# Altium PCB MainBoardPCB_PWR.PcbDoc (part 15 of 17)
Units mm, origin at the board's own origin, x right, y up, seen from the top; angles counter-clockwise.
Board outline 333.63 x 349.38 mm, 16 copper layers (L1, L2 (GND), L3 (Sign), L4 (GND), L5 (Sign), L6 (PWR/GND), L7(PWR/GND), L8 (PWR/GND), L9 (PWR/GND), L10 (PWR/GND), L11 (PWR/GND), L12 (Sign), L13 (GND), L14 (Sign), L15 (GND), L16), stack 2.503 mm thick; 2187 components, 1615 nets, 7987 pads, 1695 vias.
Unrouted connection lines stored in the file: 4757.
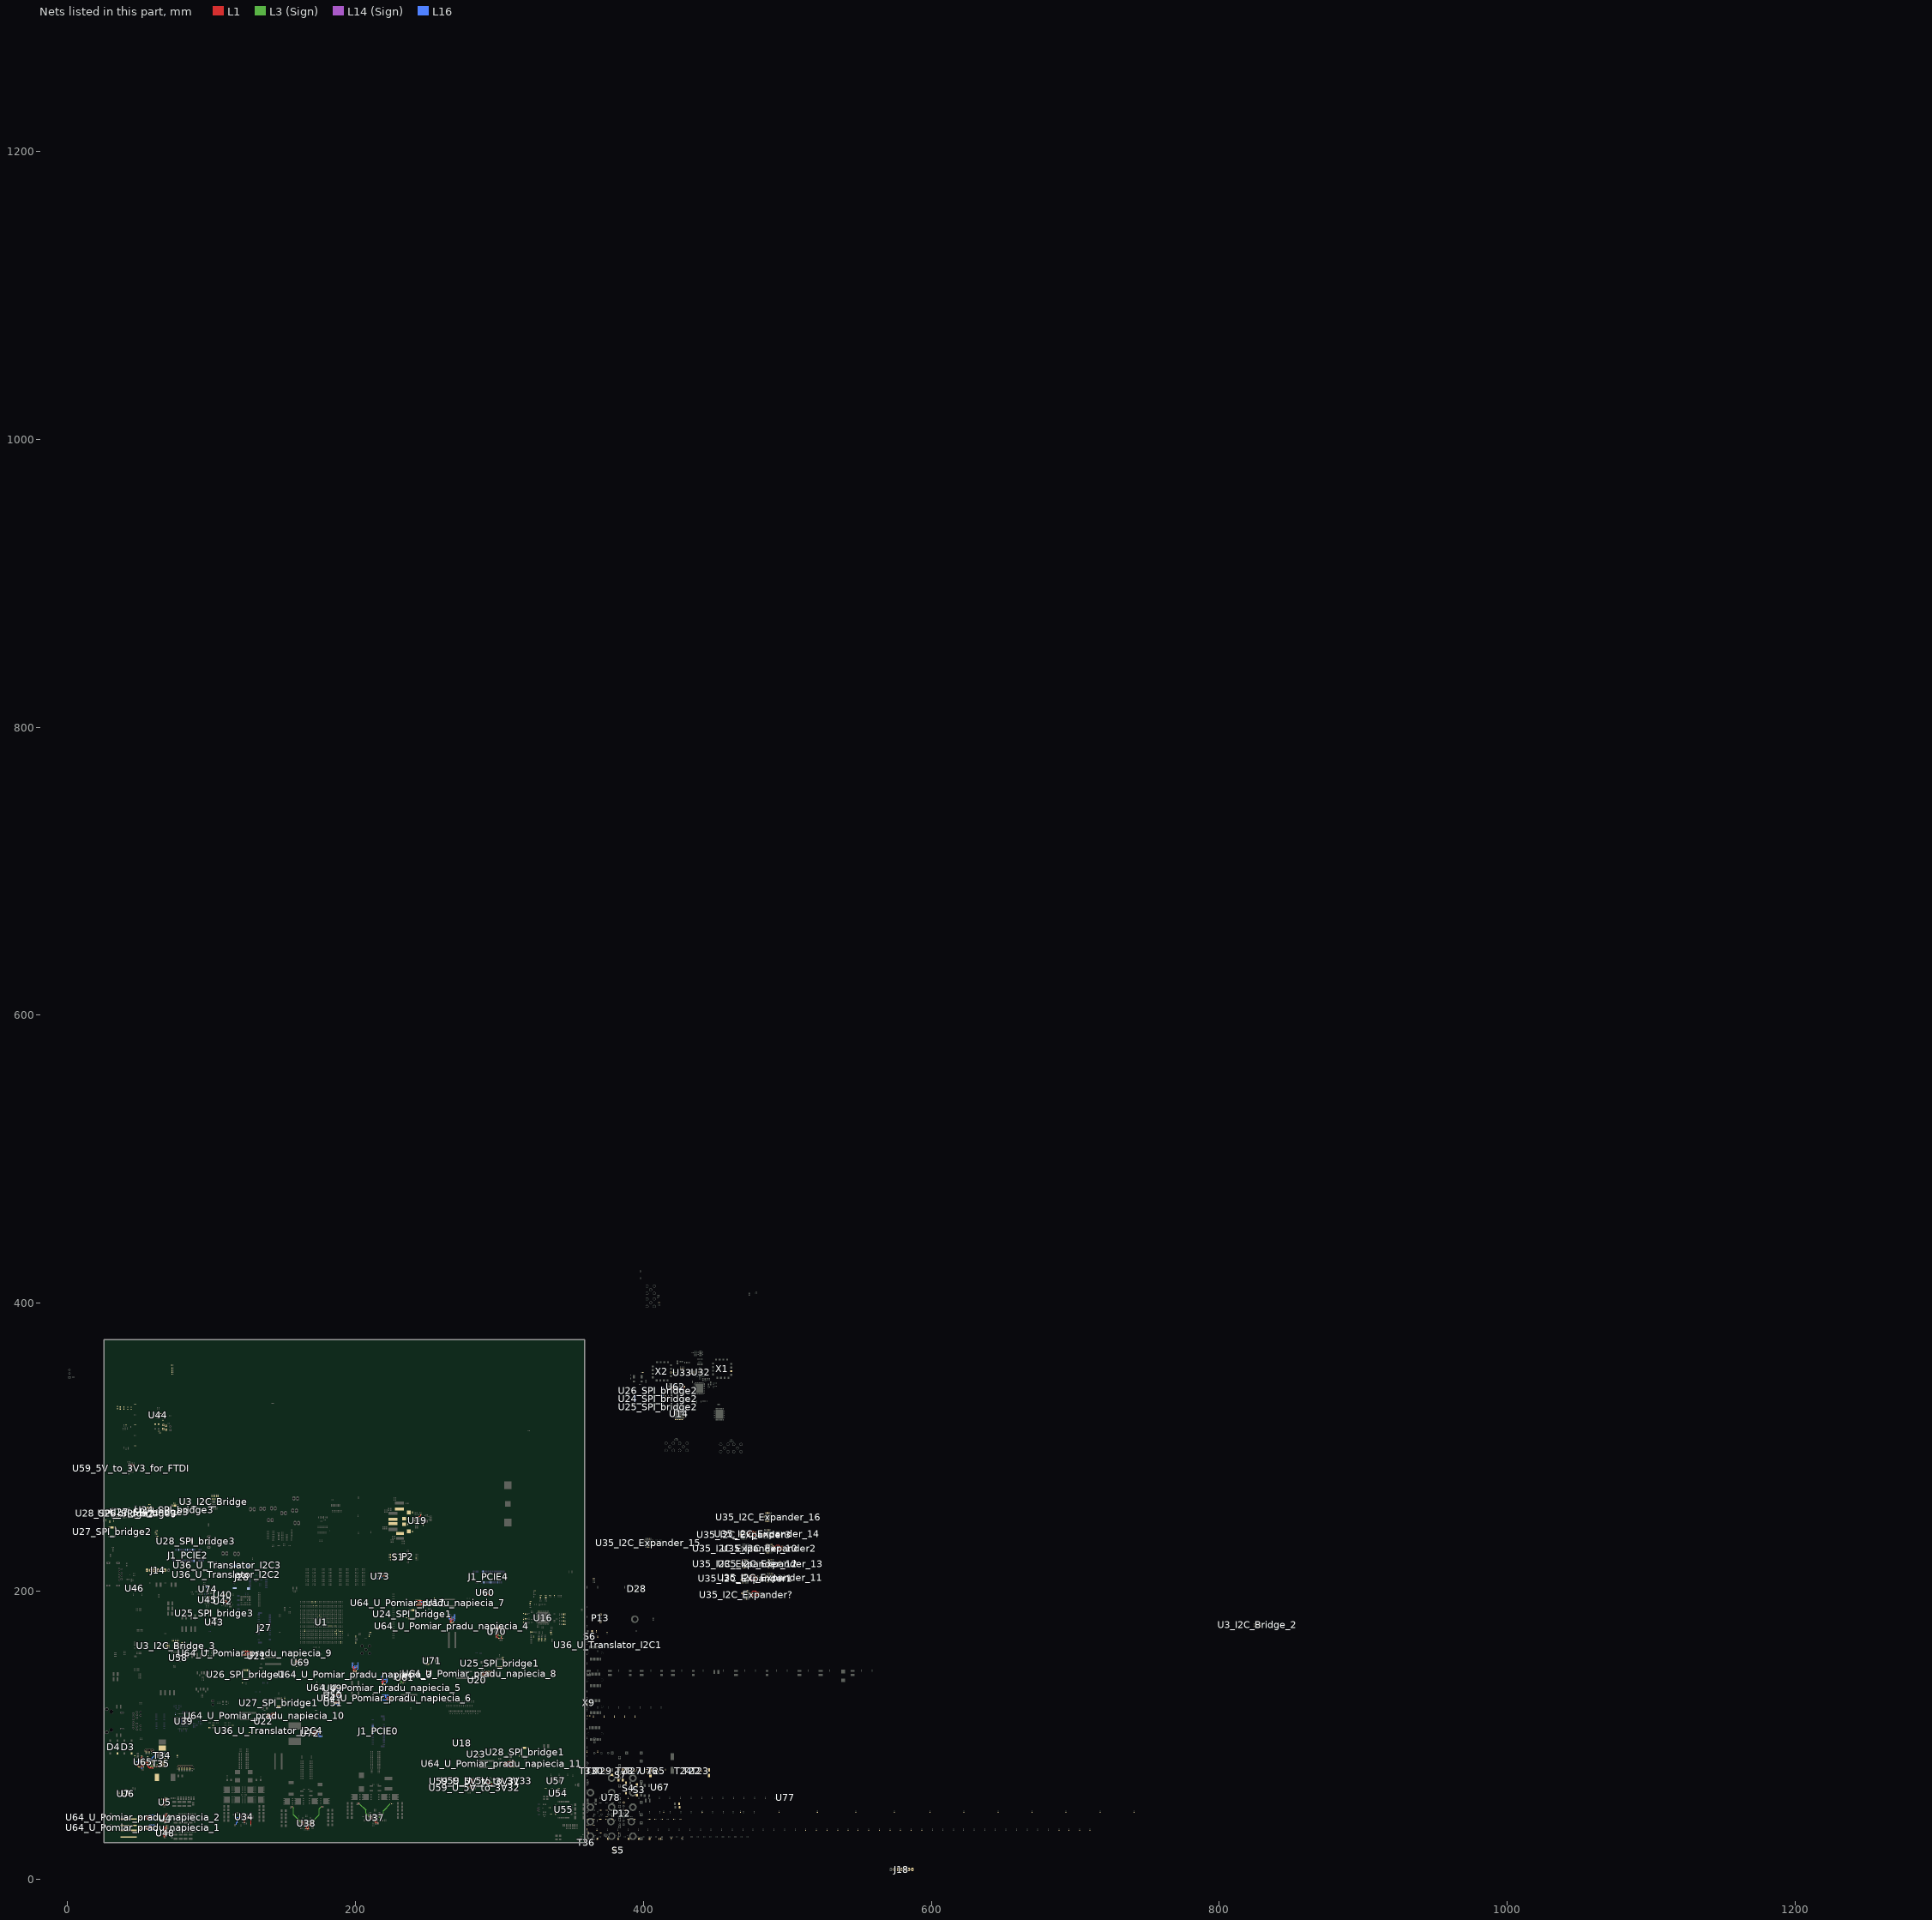
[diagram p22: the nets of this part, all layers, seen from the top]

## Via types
v1: diameter 0.5, hole 0.2, L1 to L16, 786 vias
v2: diameter 0.5/0.35/0.35/0.35/0.35/0.35/0.35/0.35/0.35/0.35/0.35/0.35/0.35/0.35/0.35/0.5 (per signal layer), hole 0.15, L1 to L16, tented both sides, 164 vias
v3: diameter 2.54, hole 1.02, L1 to L16, 152 vias
v4: diameter 0.5/0.35/0.35/0.35/0.35/0.35/0.35/0.35/0.35/0.35/0.35/0.35/0.35/0.35/0.35/0.5 (per signal layer), hole 0.2, L1 to L16, tented both sides, 100 vias
v5: diameter 0.45, hole 0.15, L1 to L16, 79 vias
v6: diameter 0.35/0/0.35 (per signal layer), hole 0.127, L1 to L3 (Sign), tented both sides, 78 vias
v7: diameter 0.45/0.45/0.45/0.45/0.45/0.45/0.45/0.45/0.45/0.45/0.45/0.45/0.45/0.45/0.45/0.45 (per signal layer), hole 0.15, L1 to L16, 65 vias
v8: diameter 0.4, hole 0.15, L1 to L16, 61 vias
v9: diameter 0.2, hole 0.1, L1 to L16, 35 vias
v10: diameter 0.5, hole 0.2, L1 to L16, tented both sides, 32 vias
v11: diameter 0.2/0/0.2 (per signal layer), hole 0.1, L1 to L3 (Sign), 28 vias
v12: diameter 0.4, hole 0.2, L1 to L16, 16 vias
v13: diameter 0.25, hole 0.2, L1 to L16, 16 vias
v14: diameter 0.3, hole 0.2, L1 to L16, 15 vias
v15: diameter 0.5/0.35/0.35/0.35/0.35/0.35/0.35/0.35/0.35/0.35/0.35/0.35/0.35/0.35/0.35/0.45 (per signal layer), hole 0.15, L1 to L16, tented both sides, 10 vias
v16: diameter 5, hole 3, L1 to L16, 9 vias
v17: diameter 0.2/0/0.2 (per signal layer), hole 0.1, L1 to L3 (Sign), tented both sides, 9 vias
v18: diameter 0.35/0/0.35 (per signal layer), hole 0.127, L1 to L3 (Sign), 7 vias
v19: diameter 0.35/0/0.35 (per signal layer), hole 0.127, L14 (Sign) to L16, tented both sides, 5 vias
v20: diameter 1.65, hole 1.65, L1 to L16, 4 vias
v21: diameter 1.15, hole 1.15, L1 to L16, 4 vias
v22: diameter 0.35, hole 0.127, L1 to L2 (GND), 2 vias
v23: diameter 0.4, hole 0.2, L1 to L16, tented both sides, 2 vias
v24: diameter 0.35, hole 0.127, L1 to L2 (GND), tented both sides, 2 vias
v25: diameter 0.508, hole 0.127, L1 to L2 (GND), 2 vias
v26: diameter 0.508, hole 0.127, L2 (GND) to L3 (Sign), 2 vias
v27: diameter 0.35, hole 0.127, L3 (Sign) to L6 (PWR/GND), tented both sides, 2 vias
v28: diameter 0.5, hole 0.2, L3 (Sign) to L6 (PWR/GND), tented both sides, 2 vias
v29: diameter 5.5, hole 3.5, L1 to L16, 1 vias
v30: diameter 0.45/0.45/0.45 (per signal layer), hole 0.15, L1 to L3 (Sign), 1 vias
v31: diameter 0.35/0.35/0.35 (per signal layer), hole 0.127, L1 to L3 (Sign), tented both sides, 1 vias
v32: diameter 0.45/0/0.45 (per signal layer), hole 0.15, L1 to L3 (Sign), tented both sides, 1 vias
v33: diameter 0.45/0/0.45 (per signal layer), hole 0.2, L14 (Sign) to L16, tented both sides, 1 vias
v34: diameter 0.35, hole 0.127, L2 (GND) to L3 (Sign), 1 vias

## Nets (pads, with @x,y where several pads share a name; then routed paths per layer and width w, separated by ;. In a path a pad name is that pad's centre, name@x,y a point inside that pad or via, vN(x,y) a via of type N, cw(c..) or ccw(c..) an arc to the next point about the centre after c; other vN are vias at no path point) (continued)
NetC657_1: C657.1 U51.6 | length 1.4
  L1 w0.254: U51.6@185.559,122.213 186.674,122.213 186.721,122.166 186.726,122.166 186.869,122.023 C657.1@186.869,122.018
NetC674_2: C674.2 FB45.1 R644.2 U69.10 U69.11 U69.12 U69.13 U69.14
NetC678_2: C678.2 R652.2 R654.2 T25.1 T29.3
NetC679_2: C679.2 D22.1 D23.1
NetC680_2: C680.2 R656.1 R657.1 T30.1
NetC693_1: C693.1 L22.1 T34.1 T34.2 T34.3 T35.5 U65.12 | length 8
  L1 w0.254: U65.12@54.172,80.707 55.15,80.707 55.518,80.339 55.518,78.52 56.907,77.13 C693.1@59.589,77.13
NetC693_2: C693.2 D26.1 R665.1 | length 2.8
  L1 w0.254: R665.1@58.578,77.884 58.591,77.897 59.576,77.897 C693.2@59.589,77.91 59.589,77.915 59.978,78.305 D26.1@59.978,79.555
NetC701_1: C701.1 R667.2 | length 1
  L1 w0.254: C701.1@49.964,77.884 49.966,77.882 R667.2@50.946,77.88 R667.2@50.946,77.88
NetC701_2: C701.2 C702.2 U65.5 | length 3.5
  L1 w0.254: C701.2@49.184,77.884 49.117,77.952 49.117,79.353 C702.2@49.049,79.42 49.054,79.42 49.197,79.563 49.197,79.568 49.233,79.604 49.233,79.82 49.619,80.207 U65.5@50.492,80.207
NetC703_2: C703.2 U65.7 | length 2.1
  L1 w0.254: U65.7@51.832,79.367 51.855,79.344 51.855,78.898 52.211,78.541 52.522,78.541 52.778,78.285 C703.2@52.778,77.832
NetC706_1: C706.1 R671.1 R672.2 U70.16 | length 3.4
  L1 w0.254: U70.16@299.259,173.698 R672.2@299.259,174.82 299.737,174.82 300.076,174.481 300.335,174.481 300.793,174.938 C706.1@300.793,175.397
NetC710_1: C710.1 R673.1 R674.2 U70.10 | length 5.3
  L1 w0.254: v11(299.253,169.141) 299.259,169.147 U70.10@299.259,169.748 ; v11(301.668,168.891) 301.618,168.891 301.445,168.718 301.445,168.532 301.313,168.4 C710.1@301.313,168.063 301.313,167.527 301.702,167.138 R674.2@301.752,167.138
  L3 (Sign) w0.254: v11(299.253,169.141) 301.417,169.141 v11(301.668,168.891)
NetC711_2: C711.2 U70.7 | length 1.6
  L1 w0.254: C711.2@297.752,168.193 297.756,168.196 297.756,169.745 U70.7@297.759,169.748
NetC712_2: C712.2 U70.19 | length 1.1
  L1 w0.254: C712.2@297.752,174.79 297.756,174.786 297.756,173.702 U70.19@297.759,173.698
NetC713_2: C713.2 U71.3 X1.14 | length 2.5
  L1 w0.254: 249.223,142.723 249.228,142.723 250.076,143.57 250.076,144.878
NetC719_2: C719.2 U69.7 | length 0.9
  L1 w0.254: U69.7@161.393,152.137 161.393,152.615 161.458,152.68 C719.2@161.458,153.027
NetC724_1: C724.1 R384.1
NetC725_1: C725.1 R385.1
NetC726_1: C726.1 R484.1
NetC727_1: C727.1 R485.1
NetC790_1: C790.1 U76.3
NetD5_1: D5.1 R716.1
NetD5_2: D5.2 U43.14
NetD6_1: D6.1 R717.1
NetD6_2: D6.2 U43.13
NetD7_1: D7.1 R718.1
NetD7_2: D7.2 D9.2 U43.12
NetD8_1: D8.1 R719.1
NetD8_2: D8.2 U43.11
NetD9_1: D9.1 R720.1
NetD10_1: D10.1 R368.1
NetD10_2: D10.2 U44.12
NetD11_2: D11.2 R370.1 S4.1 S4.2 U44.7
NetD12_2: D12.2 R369.1 S3.1 S3.2 U44.6
NetD16_1: D16.1 L13.1 U19.5
NetD16_2: D16.2 U19.6
NetD17_1: D17.1 L16.1 U19.4
NetD17_2: D17.2 U19.3
NetD18_1: D18.1 L17.1 U19.2
NetD18_2: D18.2 U19.1
NetD19_1: D19.1 L18.1 U19.7
NetD19_2: D19.2 U19.8
NetD20_1: D20.1 D21.1 R647.1
NetD20_2: D20.2 T23.3
NetD21_2: D21.2 T27.3
NetD28_2: D28.2 R276.2
NetFB29_2: FB29.2 J28.10 J28.11 J28.12 J28.13
NetJ30_1: R283.2
NetJ30_2: R286.2
NetL15_2: L15.2 U19.24 | length 3.1
  L1 w0.254: U19.24@243.724,251.458 243.724,251.925 243.873,252.074 244.901,252.074 245.449,252.622 L15.2@245.449,253.225
NetP3_1: P3.1 U44.11
NetP4_2: P4.2 U44.10
NetP12_13: P12.13 R730.1 U78.1
NetP13_1: P13.1 R675.2
NetP13_3: P13.3 R737.1
NetR3_I2C_Bridge_1: R3_I2C_Bridge.1 U3_I2C_Bridge.17
NetR3_I2C_Bridge_2_1: R3_I2C_Bridge_2.1 U3_I2C_Bridge_2.17
NetR3_I2C_Bridge_3_1: R3_I2C_Bridge_3.1 R176.1 R180.1 R185.1 R189.1 R194.1 R198.1 R203.1 R207.1 R213.1 R221.1 R538.1 U3_I2C_Bridge.19 U3_I2C_Bridge_3.17 U58.13 U64_U_Pomiar_pradu_napiecia_7.5 U64_U_Pomiar_pradu_napiecia_8.5 U64_U_Pomiar_pradu_napiecia_9.5 U64_U_Pomiar_pradu_napiecia_10.5 U64_U_Pomiar_pradu_napiecia_11.5 | length 23.6
  L1 w0.254: v8(124.91,156.531) R198.1@124.91,157.663 ; v8(126.79,155.981) 126.83,155.981 126.887,156.039 U64_U_Pomiar_pradu_napiecia_9.5@127.94,156.039 ; U64_U_Pomiar_pradu_napiecia_10.5@138.938,114.546 v8(140.288,114.546) ; R207.1@142.088,113.018 v8(142.088,114.152) ; v8(245.03,191.282) R180.1@245.03,192.759 ; v8(246.769,190.832) 246.771,190.831 U64_U_Pomiar_pradu_napiecia_7.5@248.09,190.829 U64_U_Pomiar_pradu_napiecia_7.5@248.09,190.829 ; U64_U_Pomiar_pradu_napiecia_8.5@288.331,143.579 v8(289.281,143.579) ; R189.1@291.357,141.943 R185.1@291.357,143.229 v8(291.357,143.379) ; U64_U_Pomiar_pradu_napiecia_11.5@303.702,80.993 v8(304.965,80.993) ; R221.1@307.166,78.891 v8(307.166,80.768)
  L16 w0.254: v8(124.91,156.531) 125.46,155.981 v8(126.79,155.981) ; v8(140.288,114.546) 141.694,114.546 v8(142.088,114.152) ; v8(245.03,191.282) 245.48,190.832 v8(246.769,190.832) ; v8(289.281,143.579) 289.481,143.379 v8(291.357,143.379) ; v8(304.965,80.993) 305.005,80.993 305.23,80.768 v8(307.166,80.768)
NetR4_I2C_Bridge_1: R4_I2C_Bridge.1 U3_I2C_Bridge.16
NetR4_I2C_Bridge_2_1: R4_I2C_Bridge_2.1 U3_I2C_Bridge_2.16
NetR4_I2C_Bridge_3_1: R4_I2C_Bridge_3.1 R177.1 R181.1 R186.1 R190.1 R195.1 R199.1 R204.1 R208.1 R215.1 R222.1 R427.1 U3_I2C_Bridge.20 U3_I2C_Bridge_3.16 U58.14 U64_U_Pomiar_pradu_napiecia_7.4 U64_U_Pomiar_pradu_napiecia_8.4 U64_U_Pomiar_pradu_napiecia_9.4 U64_U_Pomiar_pradu_napiecia_10.4 U64_U_Pomiar_pradu_napiecia_11.4 | length 30.3
  L1 w0.254: R195.1@123.852,156.531 v8(123.852,157.663) ; v8(126.79,156.656) 126.83,156.656 126.947,156.539 U64_U_Pomiar_pradu_napiecia_9.4@127.94,156.539 ; U64_U_Pomiar_pradu_napiecia_10.4@138.938,114.046 v8(139.888,114.046) ; R208.1@143.053,113.018 v8(143.053,113.143) R204.1@143.053,114.282 ; R177.1@244.014,191.282 v8(244.014,192.709) R181.1@244.014,192.759 ; v8(246.769,191.479) 246.809,191.479 246.959,191.329 U64_U_Pomiar_pradu_napiecia_7.4@248.09,191.329 ; U64_U_Pomiar_pradu_napiecia_8.4@288.331,143.079 288.354,143.056 289.114,143.056 289.241,142.929 v8(289.281,142.929) ; v8(292.357,142.068) R186.1@292.357,143.229 ; U64_U_Pomiar_pradu_napiecia_11.4@303.702,80.493 304.671,80.493 304.821,80.343 v8(304.86,80.343) ; R222.1@308.227,78.891 R215.1@308.227,80.768
  L16 w0.254: v8(123.852,157.663) 125.783,157.663 v8(126.79,156.656) ; v8(139.888,114.046) 140.791,113.143 v8(143.053,113.143) ; v8(244.014,192.709) 245.539,192.709 v8(246.769,191.479) ; v8(289.281,142.929) 290.142,142.068 v8(292.357,142.068) ; v8(304.86,80.343) 306.462,78.741 v8(308.227,78.741)
NetR5_I2C_Bridge_1: R5_I2C_Bridge.1 U3_I2C_Bridge.15
NetR5_I2C_Bridge_2_1: R5_I2C_Bridge_2.1 U3_I2C_Bridge_2.15
NetR5_I2C_Bridge_3_1: R5_I2C_Bridge_3.1 U3_I2C_Bridge_3.15 U35_I2C_Expander3.8
NetR6_I2C_Bridge_1: R6_I2C_Bridge.1 U3_I2C_Bridge.14
NetR6_I2C_Bridge_2_1: R6_I2C_Bridge_2.1 U3_I2C_Bridge_2.14
NetR6_I2C_Bridge_3_1: R6_I2C_Bridge_3.1 U3_I2C_Bridge_3.14 U35_I2C_Expander3.9
NetR7_I2C_Bridge_1: R7_I2C_Bridge.1 U3_I2C_Bridge.13
NetR7_I2C_Bridge_2_1: R7_I2C_Bridge_2.1 U3_I2C_Bridge_2.13
NetR7_I2C_Bridge_3_1: R7_I2C_Bridge_3.1 R130.1 U3_I2C_Bridge_3.13
NetR8_I2C_Bridge_1: R8_I2C_Bridge.1 U3_I2C_Bridge.12
NetR8_I2C_Bridge_2_1: R8_I2C_Bridge_2.1 U3_I2C_Bridge_2.12
NetR8_I2C_Bridge_3_1: R8_I2C_Bridge_3.1 R131.1 U3_I2C_Bridge_3.12
NetR9_I2C_Bridge_2_1: R9_I2C_Bridge_2.1 U3_I2C_Bridge_2.11
NetR9_I2C_Bridge_3_1: R9_I2C_Bridge_3.1 R22.1 R389.1 R457.1 R465.1 R563.1 R567.1 R571.1 R575.1 R579.1 R583.1 R587.1 R591.1 R593.1 R597.1 U3_I2C_Bridge_3.11 U35_I2C_Expander1.8 U35_I2C_Expander2.8 U64_U_Pomiar_pradu_napiecia_1.5 U64_U_Pomiar_pradu_napiecia_2.5 U64_U_Pomiar_pradu_napiecia_3.5 U64_U_Pomiar_pradu_napiecia_4.5 U64_U_Pomiar_pradu_napiecia_5.5 U64_U_Pomiar_pradu_napiecia_6.5 U72.5 | length 39.6
  L1 w0.164: U64_U_Pomiar_pradu_napiecia_5.5@218.753,135.604 218.753,138.01 219.352,138.609 v4(219.352,138.865)
  L1 w0.254: U64_U_Pomiar_pradu_napiecia_1.5@54.676,36.768 58.159,36.768 58.299,36.628 v8(58.339,36.628) ; U64_U_Pomiar_pradu_napiecia_2.5@54.676,43.783 58.174,43.783 58.299,43.658 v8(58.339,43.658) ; U72.5@170.431,102.245 174.133,102.245 v8(174.687,101.691) ; U64_U_Pomiar_pradu_napiecia_3.5@198.796,144.262 198.796,147.009 199.036,147.249 v8@199.036,148.149 ; v8(220.909,125.43) 221.634,124.705 U64_U_Pomiar_pradu_napiecia_6.5@224.78,124.705 ; U64_U_Pomiar_pradu_napiecia_4.5@266.005,178.019 266.005,180.621 266.43,181.046 v8(266.43,181.846)
  L16 w0.254: R465.1@58.339,35.163 v8(58.339,36.628) ; R597.1@58.339,41.9 v8(58.339,43.658) ; R389.1@174.687,100.145 v8(174.687,101.691) ; R563.1@199.036,148.149 R567.1@200.961,148.149 ; R579.1@219.302,138.865 v4(219.352,138.865) R583.1@221.209,138.865 ; R587.1@220.909,125.305 v8(220.909,125.43) R591.1@220.909,126.878 ; R571.1@266.305,181.846 v8(266.43,181.846) R575.1@268.155,181.846
  other v8: 198.919,148.246
NetR10_I2C_Bridge_2_1: R10_I2C_Bridge_2.1 U3_I2C_Bridge_2.10
NetR10_I2C_Bridge_3_1: R10_I2C_Bridge_3.1 R24.1 R390.1 R459.1 R466.1 R564.1 R568.1 R572.1 R576.1 R580.1 R584.1 R588.1 R592.1 R594.1 R598.1 U3_I2C_Bridge_3.10 U35_I2C_Expander1.9 U35_I2C_Expander2.9 U64_U_Pomiar_pradu_napiecia_1.4 U64_U_Pomiar_pradu_napiecia_2.4 U64_U_Pomiar_pradu_napiecia_3.4 U64_U_Pomiar_pradu_napiecia_4.4 U64_U_Pomiar_pradu_napiecia_5.4 U64_U_Pomiar_pradu_napiecia_6.4 U72.4 | length 37.1
  L1 w0.164: U64_U_Pomiar_pradu_napiecia_5.4@219.253,135.17 219.253,136.543 219.253,136.977 219.935,137.658 v4(221.147,137.658)
  L1 w0.254: U64_U_Pomiar_pradu_napiecia_1.4@54.676,36.267 56.193,36.267 v8(57.298,35.163) ; U64_U_Pomiar_pradu_napiecia_2.4@54.676,43.283 55.881,43.283 v8(57.264,41.9) ; U72.4@170.431,101.745 172.074,101.745 v8(173.68,100.139) ; U64_U_Pomiar_pradu_napiecia_3.4@199.296,144.262 199.296,145.539 200.961,147.204 v8(200.961,147.226) ; v8(221.959,126.883) 223.637,125.205 U64_U_Pomiar_pradu_napiecia_6.4@224.78,125.205 ; U64_U_Pomiar_pradu_napiecia_4.4@266.505,178.019 266.505,179.256 v8(268.151,180.903)
  L16 w0.254: v8(57.264,41.9) R594.1@57.264,43.654 ; v8(57.298,35.163) R459.1@57.298,36.628 ; v8(173.68,100.139) R24.1@173.68,101.691 ; R564.1@198.911,147.2 198.937,147.226 v8(200.961,147.226) R568.1@200.961,147.2 ; R580.1@219.302,137.658 v4(221.147,137.658) R584.1@221.197,137.658 ; R588.1@221.959,125.305 v8(221.959,126.883) ; R572.1@266.305,180.907 266.309,180.903 v8(268.151,180.903) R576.1@268.155,180.907
NetR12_1: R12.1 R19.2 U5.5 | length 2
  L1 w0.254: R12.1@66.449,55.624 66.474,55.649 67.389,55.649 67.487,55.649 R19.2@67.512,55.674 ; U5.5@67.379,54.595 67.379,55.169 67.389,55.179 R19.2@67.389,55.551
NetR14_2: R14.2 R16.2 R22.2 R24.2 U72.2 | length 7.1
  L1 w0.254: U72.2@170.431,100.745 171.376,100.745 171.593,100.963 v8(171.633,100.963)
  L16 w0.254: v8(171.633,100.963) 173.261,102.591 R24.2@173.68,102.591 R16.2@176.728,102.591
NetR15_1: R15.1 R23.2 U4.5 | length 2.2
  L1 w0.254: R15.1@66.63,44.35 66.652,44.371 67.539,44.371 R23.2@67.56,44.393 U4.5@67.56,43.15
NetR17_1: R17.1 R25.2 U4.4 | length 2.8
  L1 w0.254: U4.4@68.06,43.15 68.06,43.628 68.087,43.655 68.087,44.088 68.693,44.693 R17.1@68.743,44.693 R25.2@68.743,45.643
NetR18_2: R18.2 U4.10 | length 1.4
  L1 w0.254: U4.10@67.56,40.85 67.587,40.823 67.587,40.602 67.96,40.229 R18.2@67.96,39.6
NetR20_1: R20.1 R26.2 U5.4 | length 2.2
  L1 w0.254: U5.4@67.879,54.595 67.906,54.622 67.906,54.99 68.512,55.595 R20.1@68.562,55.595 R26.2@68.562,56.524
NetR21_2: R21.2 U5.10 | length 1.1
  L1 w0.254: U5.10@67.412,52.049 67.412,52.042 67.815,51.639 67.815,51.151 R21.2@67.854,51.111
NetR27_2: R27.2 U6.C1
NetR28_2: R28.2 U7.C1
NetR149_1: R149.1 R159.2 U65.20 | length 3
  L1 w0.254: U65.20@51.332,83.047 51.332,84.377 51.732,84.777 R149.1@51.782,84.777 51.769,84.79 51.769,85.774 R159.2@51.757,85.787
NetR150_1: R150.1 R160.2 U65.6 | length 3.8
  L1 w0.254: U65.6@51.332,79.367 51.332,78.482 51.883,77.93 v9(51.883,77.905) ; v9(51.832,75.895) R150.1@51.882,75.895
  L16 w0.254: v9(51.832,75.895) 51.832,77.854 v9(51.883,77.905)
NetR174_2: R174.2 R175.2 R176.2 R177.2 U64_U_Pomiar_pradu_napiecia_7.2 | length 7.4
  L1 w0.254: R175.2@241.934,190.382 R176.2@245.03,190.382 245.604,190.382 246.154,190.932 246.154,191.715 246.769,192.329 U64_U_Pomiar_pradu_napiecia_7.2@248.09,192.329
NetR178_2: R178.2 R179.2 R180.2 R181.2 U64_U_Pomiar_pradu_napiecia_7.1 | length 6.5
  L1 w0.254: R179.2@241.934,193.659 R178.2@242.95,193.659 R181.2@244.014,193.659 R180.2@245.03,193.659 246.154,193.659 246.984,192.829 U64_U_Pomiar_pradu_napiecia_7.1@248.09,192.829
NetR182_2: R182.2 U17.C1
NetR183_2: R183.2 R184.2 R185.2 R186.2 U64_U_Pomiar_pradu_napiecia_8.2 | length 7.8
  L1 w0.254: U64_U_Pomiar_pradu_napiecia_8.2@288.331,142.079 289.636,142.079 290.021,142.464 290.021,143.98 290.17,144.129 R184.2@294.357,144.129
NetR187_2: R187.2 R188.2 R189.2 R190.2 U64_U_Pomiar_pradu_napiecia_8.1 | length 6.2
  L1 w0.254: U64_U_Pomiar_pradu_napiecia_8.1@288.331,141.579 289.636,141.579 290.172,141.043 R189.2@291.357,141.043 R188.2@294.357,141.043
NetR191_2: R191.2 U20.C1
NetR192_2: R192.2 R193.2 R194.2 R195.2 U64_U_Pomiar_pradu_napiecia_9.2 | length 7.5
  L1 w0.254: R193.2@121.735,155.631 R192.2@122.794,155.631 R195.2@123.852,155.631 R194.2@124.91,155.631 124.973,155.694 125.839,155.694 126.363,156.219 126.363,156.998 126.904,157.539 U64_U_Pomiar_pradu_napiecia_9.2@127.94,157.539
NetR196_2: R196.2 R197.2 R198.2 R199.2 U64_U_Pomiar_pradu_napiecia_9.1 | length 6.4
  L1 w0.254: R197.2@121.735,158.563 R196.2@122.794,158.563 R199.2@123.852,158.563 R198.2@124.91,158.563 125.839,158.563 126.363,158.039 U64_U_Pomiar_pradu_napiecia_9.1@127.94,158.039
NetR200_2: R200.2 U21.C1
NetR201_2: R201.2 R202.2 R203.2 R204.2 U64_U_Pomiar_pradu_napiecia_10.2 | length 6.9
  L1 w0.254: U64_U_Pomiar_pradu_napiecia_10.2@138.938,113.046 139.841,113.046 141.749,114.954 141.915,114.954 142.088,115.127 R203.2@142.088,115.177 R201.2@144.008,115.177 R202.2@144.958,115.177
NetR205_2: R205.2 R206.2 R207.2 R208.2 U64_U_Pomiar_pradu_napiecia_10.1 | length 6.2
  L1 w0.254: U64_U_Pomiar_pradu_napiecia_10.1@138.938,112.546 140.288,112.546 140.716,112.118 R207.2@142.088,112.118 R208.2@143.053,112.118 144.955,112.118 R206.2@144.958,112.121
NetR209_2: R209.2 U22.C1
NetR210_2: R210.2 R211.2 R213.2 R215.2 U64_U_Pomiar_pradu_napiecia_11.2 | length 8.3
  L1 w0.254: U64_U_Pomiar_pradu_napiecia_11.2@303.702,79.493 305.13,79.493 305.66,80.023 305.66,81.318 306.01,81.668 R213.2@307.166,81.668 R211.2@310.314,81.668
NetR217_2: R217.2 R219.2 R221.2 R222.2 U64_U_Pomiar_pradu_napiecia_11.1 | length 7
  L1 w0.254: U64_U_Pomiar_pradu_napiecia_11.1@303.702,78.993 305.078,78.993 306.08,77.991 R221.2@307.166,77.991 307.168,77.989 310.312,77.989 R219.2@310.314,77.987
NetR223_I2C_Bridge_2_1: R223_I2C_Bridge_2.1 U3_I2C_Bridge_2.8
NetR224_I2C_Bridge_2_1: R224_I2C_Bridge_2.1 U3_I2C_Bridge_2.7
NetR225_I2C_Bridge_2_1: R225_I2C_Bridge_2.1 U3_I2C_Bridge_2.6
NetR226_I2C_Bridge_2_1: R226_I2C_Bridge_2.1 U3_I2C_Bridge_2.5
NetR227_I2C_Bridge_2_1: R227_I2C_Bridge_2.1 U3_I2C_Bridge_2.4 U35_I2C_Expander_14.8 U35_I2C_Expander_15.8 U35_I2C_Expander_16.8
NetR228_2: R228.2 U23.C1
NetR229_2: R229.2 R230.2 R457.2 R459.2 U64_U_Pomiar_pradu_napiecia_1.2 | length 7.4
  L1 w0.254: U64_U_Pomiar_pradu_napiecia_1.2@54.676,35.267 55.618,35.267 55.833,35.483 v8(55.873,35.483)
  L16 w0.254: v8(55.873,35.483) 55.873,36.667 56.733,37.528 R459.2@57.298,37.528 R230.2@60.465,37.528
NetR231_SPI_bridge3_1: R231_SPI_bridge3.1 U24_SPI_bridge3.11
NetR231_SPI_bridge3_2: R231_SPI_bridge3.2 U24_SPI_bridge3.15
NetR232_SPI_bridge1_2: R232_SPI_bridge1.2 U24_SPI_bridge1.9
NetR232_SPI_bridge2_2: R232_SPI_bridge2.2 U24_SPI_bridge2.9
NetR232_SPI_bridge3_2: R232_SPI_bridge3.2 U24_SPI_bridge3.9
NetR233_SPI_bridge3_1: R233_SPI_bridge3.1 U24_SPI_bridge1.6 U25_SPI_bridge1.6 U25_SPI_bridge3.11 U26_SPI_bridge1.6 U27_SPI_bridge1.6 U28_SPI_bridge1.6
NetR234_SPI_bridge1_2: R234_SPI_bridge1.2 U25_SPI_bridge1.9
NetR234_SPI_bridge2_2: R234_SPI_bridge2.2 U25_SPI_bridge2.9
NetR234_SPI_bridge3_2: R234_SPI_bridge3.2 U25_SPI_bridge3.9
NetR235_SPI_bridge1_1: R235_SPI_bridge1.1 U26_SPI_bridge1.9
NetR235_SPI_bridge2_1: R235_SPI_bridge2.1 U26_SPI_bridge2.9
NetR235_SPI_bridge3_1: R235_SPI_bridge3.1 U26_SPI_bridge3.9
NetR237_SPI_bridge1_1: R237_SPI_bridge1.1 U27_SPI_bridge1.9
NetR237_SPI_bridge2_1: R237_SPI_bridge2.1 U27_SPI_bridge2.9
NetR237_SPI_bridge3_1: R237_SPI_bridge3.1 U27_SPI_bridge3.9
NetR238_SPI_bridge2_1: R238_SPI_bridge2.1 U27_SPI_bridge2.11
NetR238_SPI_bridge2_2: R238_SPI_bridge2.2 U27_SPI_bridge2.15
NetR238_SPI_bridge3_1: R238_SPI_bridge3.1 U27_SPI_bridge3.11
NetR238_SPI_bridge3_2: R238_SPI_bridge3.2 U27_SPI_bridge3.15
NetR239_SPI_bridge1_2: R239_SPI_bridge1.2 U28_SPI_bridge1.9
NetR239_SPI_bridge2_2: R239_SPI_bridge2.2 U28_SPI_bridge2.9
NetR239_SPI_bridge3_2: R239_SPI_bridge3.2 U28_SPI_bridge3.9
NetR240_SPI_bridge3_1: R240_SPI_bridge3.1 U28_SPI_bridge3.11
NetR240_SPI_bridge3_2: R240_SPI_bridge3.2 U28_SPI_bridge3.15
NetR241_1: R241.1 R242.1 U3_I2C_Bridge_2.22
NetR243_1: R243.1 R244.1 U3_I2C_Bridge_2.23
NetR263_2: R263.2 U33.16
NetR264_2: R264.2 U33.13
NetR265_2: R265.2 U33.15
NetR266_1: R266.1 R267.2 S5.1 S5.2 S5.3 S5.4
NetR269_2: R269.2 U18.C1
NetR272_1: R272.1 U34.5 | length 1.8
  L1 w0.254: R272.1@122.978,39.14 U34.5@122.977,40.906
NetR281_1: R281.1 R400.1 U3_I2C_Bridge_2.18
NetR284_2: R284.2 U19.17
NetR289_1: R289.1 U37.5 | length 1.4
  L1 w0.254: R289.1@213.795,38.966 U37.5@213.795,40.359
NetR293_2: R293.2 R294.2 U37.7 | length 2.4
  L1 w0.254: U37.7@214.795,40.359 R293.2@214.795,38.966 R294.2@215.795,38.966
NetR304_2: R304.2 R388.2 R389.2 R390.2 U72.1 | length 6.7
  L1 w0.254: U72.1@170.431,100.245 171.487,100.245 171.593,100.139 v8(171.633,100.139)
  L16 w0.254: v8(171.633,100.139) 172.533,99.239 R388.2@176.728,99.239
NetR305_2: R305.2 U67.6
NetR307_1: R307.1 U38.5 | length 1.8
  L1 w0.254: R307.1@165.608,34.987 165.608,35.037 166.283,35.712 U38.5@166.283,36.515
NetR308_2: R308.2 U67.5
NetR309_2: R309.2 U67.4
NetR310_2: R310.2 R312.2 U38.7 | length 2.5
  L1 w0.254: R310.2@166.533,34.987 R312.2@167.448,34.987 167.448,35.745 167.283,35.91 U38.7@167.283,36.515
NetR334_1: R334.1 U39.12
NetR339_1: R339.1 R341.2 U40.7 | length 2.6
  L1 w0.164: U40.7@109.116,197.66 R339.1@110.692,197.66 R341.2@110.692,196.635
NetR342_1: R342.1 R344.2 U42.7 | length 2.3
  L1 w0.164: U42.7@109.117,193.373 109.242,193.373 109.336,193.279 R342.1@110.39,193.279 ; R344.2@110.39,192.073 110.392,192.075 R342.1@110.392,193.102
NetR358_1: R358.1 S1.8
NetR359_1: R359.1 S1.7
NetR360_1: R360.1 S1.6
NetR361_1: R361.1 S1.5
NetR366_2: R366.2 R498.1 R499.2 R692.2
NetR372_1: R372.1 R373.2 U44.2 U44.3
NetR379_2: R379.2 U45.24
NetR380_2: R380.2 U46.C1
NetR391_1: R391.1 R393.2 U49.7 | length 3.5
  L1 w0.254: U49.7@185.559,132.959 187.374,132.959 187.523,132.811 187.523,132.618 R393.2@187.696,132.445 187.721,132.47 188.7,132.47 R391.1@188.725,132.495
NetR394_1: R394.1 R396.2 U50.7 | length 3.8
  L1 w0.254: U50.7@185.559,128.11 185.607,128.158 188.126,128.158 R394.1@188.22,128.252 R396.2@188.22,127.169
NetR397_1: R397.1 R399.2 U51.7 | length 3.9
  L1 w0.254: U51.7@185.559,122.863 186.314,122.863 186.575,123.125 R397.1@188.266,123.125 R399.2@188.266,122.059
NetR419_2: R419.2 R422.1 U54.1
NetR423_2: R423.2 U55.6
NetR424_2: R424.2 U55.14
NetR428_1: R428.1 U3_I2C_Bridge_2.20 U35_I2C_Expander?.9 U36_U_Translator_I2C1.5 U36_U_Translator_I2C2.5
NetR429_1: R429.1 U58.12
NetR430_5V_to_3V3_for_FTDI_1: R430_5V_to_3V3_for_FTDI.1 R432_5V_to_3V3_for_FTDI.2 U59_5V_to_3V3_for_FTDI.7 | length 2.8
  L1 w0.254: U59_5V_to_3V3_for_FTDI.7@43.751,286.64 43.751,287.194 44.222,287.665 R432_5V_to_3V3_for_FTDI.2@44.222,288.192 R430_5V_to_3V3_for_FTDI.1@45.226,288.192
NetR430_U_5V_to_3V31_1: R430_U_5V_to_3V31.1 R432_U_5V_to_3V31.2 U59_U_5V_to_3V31.7 | length 1.5
  L1 w0.254: R430_U_5V_to_3V31.1@280.294,67.459 280.962,67.459 281.162,67.659 U59_U_5V_to_3V31.7@281.697,67.659
NetR430_U_5V_to_3V32_1: R430_U_5V_to_3V32.1 R432_U_5V_to_3V32.2 U59_U_5V_to_3V32.7 | length 3.7
  L1 w0.254: R432_U_5V_to_3V32.2@278.529,64.209 279.936,64.209 280.386,63.759 R430_U_5V_to_3V32.1@280.386,63.209 U59_U_5V_to_3V32.7@281.454,63.209
NetR430_U_5V_to_3V33_1: R430_U_5V_to_3V33.1 R432_U_5V_to_3V33.2 U59_U_5V_to_3V33.7 | length 4.5
  L1 w0.254: U59_U_5V_to_3V33.7@292.231,68.634 292.712,68.634 v11(292.766,68.581) ; R432_U_5V_to_3V33.2@294.81,65.516 v11(294.81,66.603)
  L3 (Sign) w0.254: v11(292.766,68.581) 294.743,66.603 v11(294.81,66.603)
NetR431_5V_to_3V3_for_FTDI_1: R431_5V_to_3V3_for_FTDI.1 U59_5V_to_3V3_for_FTDI.5 | length 2.1
  L1 w0.254: U59_5V_to_3V3_for_FTDI.5@45.051,286.64 45.051,286.765 46.094,287.808 46.094,288.019 R431_5V_to_3V3_for_FTDI.1@46.267,288.192
NetR433_1: R433.1 R434.2 U60.9 | length 2.5
  L1 w0.254: U60.9@291.715,198.056 291.865,198.056 292.369,197.553 R434.2@292.935,197.553 R433.1@292.935,198.582
NetR435_1: R435.1 R668.2 U69.4
NetR443_1: R443.1 R444.2 U62.6 | length 5.8
  L1 w0.254: U62.6@423.755,340.842 v9(424.26,340.842) ; v9(427.76,340.542) 427.76,340.592 428.187,341.019 428.187,341.594 R443.1@428.535,341.942
  L16 w0.254: v9(424.26,340.842) 427.46,340.842 v9(427.76,340.542)
NetR449_1: R449.1 R450.1 U3_I2C_Bridge.22
NetR451_1: R451.1 R452.1 U3_I2C_Bridge.23
NetR453_1: R453.1 R454.1 U3_I2C_Bridge.18
NetR455_1: R455.1 R456.1 U35_I2C_Expander1.13 | length 6.7
  L1 w0.254: U35_I2C_Expander1.13@473.761,210.017 474.528,210.017 475.728,211.217 477.016,211.217 477.272,210.961 R455.1@477.272,210.411 R456.1@479.304,210.411
NetR458_1: R458.1 R460.1 U35_I2C_Expander1.12 | length 6.6
  L1 w0.254: U35_I2C_Expander1.12@473.761,209.367 v1(475.297,209.367) ; R458.1@477.272,209.367 v1(478.31,209.367) R460.1@479.304,209.367
  L14 (Sign) w0.254: v1(475.297,209.367) v1(478.31,209.367)
NetR461_2: R461.2 R463.2 R465.2 R466.2 U64_U_Pomiar_pradu_napiecia_1.1 | length 6
  L1 w0.254: U64_U_Pomiar_pradu_napiecia_1.1@54.676,34.768 55.733,34.768 55.833,34.667 v8(55.873,34.667)
  L16 w0.254: v8(55.873,34.667) 56.277,34.263 R466.2@57.298,34.263 57.303,34.268 60.46,34.268 R463.2@60.465,34.274
NetR462_1: R462.1 R464.1 U35_I2C_Expander1.11 | length 6.5
  L1 w0.254: U35_I2C_Expander1.11@473.761,208.717 474.663,208.717 475.728,207.651 476.979,207.651 477.272,207.945 R462.1@477.272,208.345 R464.1@479.304,208.345
NetR467_2: R467.2 R468.2 R593.2 R594.2 U64_U_Pomiar_pradu_napiecia_2.2 | length 7.6
  L1 w0.254: U64_U_Pomiar_pradu_napiecia_2.2@54.676,42.283 55.722,42.283 55.833,42.394 v8(55.873,42.394)
  L16 w0.254: v8(55.873,42.394) 55.873,43.683 56.733,44.543 57.254,44.543 R594.2@57.264,44.554 57.268,44.557 60.527,44.557 R468.2@60.53,44.561
NetR469_1: R469.1 R470.1 U3_I2C_Bridge_3.22
NetR471_1: R471.1 R472.1 U3_I2C_Bridge_3.23
NetR473_1: R473.1 R474.1 U3_I2C_Bridge_3.18
NetR475_1: R475.1 R476.1 U35_I2C_Expander3.13 | length 6.5
  L1 w0.254: 472.72,239.27 473.363,239.27 474.513,238.12 475.937,238.12 476.234,238.416 476.234,238.839 R475.1@476.289,238.894 ; R475.1@476.261,238.866 478.066,238.866 R476.1@478.101,238.902
NetR477_1: R477.1 R478.1 U35_I2C_Expander3.12 | length 6.7
  L1 w0.254: U35_I2C_Expander3.12@472.72,239.92 472.726,239.925 v1(474.17,239.925) ; R477.1@476.293,239.931 R477.1@476.293,239.931 v1(477.258,239.932) ; 476.881,239.939 R478.1@478.105,239.939
  L14 (Sign) w0.254: v1(474.17,239.925) 477.252,239.925 v1(477.258,239.932)
NetR479_1: R479.1 R480.1 U35_I2C_Expander3.11 | length 6.4
  L1 w0.254: 472.72,240.57 473.095,240.57 474.295,241.77 475.879,241.77 476.293,241.356 R479.1@476.293,240.976 ; R479.1@476.293,240.983 R480.1@478.105,240.983
NetR481_2: R481.2 U26_SPI_bridge3.13
NetR488_1: R488.1 T36.3 U32.2
NetR543_1: R543.1 X9.3
NetR544_1: R544.1 X9.1
NetR558_I2C_Bridge_2_1: R558_I2C_Bridge_2.1 U3_I2C_Bridge_2.3 U35_I2C_Expander_14.9 U35_I2C_Expander_15.9 U35_I2C_Expander_16.9
NetR561_2: R561.2 R562.2 R563.2 R564.2 U64_U_Pomiar_pradu_napiecia_3.2 | length 7
  L1 w0.254: v8(200.098,145.284) 200.098,145.266 200.296,145.068 U64_U_Pomiar_pradu_napiecia_3.2@200.296,144.262
  L16 w0.254: R561.2@198.011,149.079 198.011,148.149 198.011,147.2 198.112,147.098 198.112,146.722 198.361,146.474 198.909,146.474 v8(200.098,145.284) ; R561.2@198.019,149.246 R562.2@198.019,150.181
NetR565_2: R565.2 R566.2 R567.2 R568.2 U64_U_Pomiar_pradu_napiecia_3.1 | length 6.5
  L1 w0.254: U64_U_Pomiar_pradu_napiecia_3.1@200.796,144.262 200.796,145.078 200.997,145.279 v8(200.997,145.294)
  L16 w0.254: v8(200.997,145.294) 201.861,146.157 R568.2@201.861,147.2 ; R568.2@201.861,147.2 201.861,149.646 R566.2@201.861,150.265 R566.2@201.911,150.265
NetR569_2: R569.2 R570.2 R571.2 R572.2 U64_U_Pomiar_pradu_napiecia_4.2 | length 6.9
  L1 w0.254: v8(267.324,178.992) 267.324,178.952 267.482,178.794 267.482,178.042 U64_U_Pomiar_pradu_napiecia_4.2@267.505,178.019
  L16 w0.254: R570.2@265.405,183.751 R569.2@265.405,182.786 R571.2@265.405,181.846 R572.2@265.405,180.907 265.405,180.391 265.633,180.162 266.153,180.162 v8(267.324,178.992)
NetR573_2: R573.2 R574.2 R575.2 R576.2 U64_U_Pomiar_pradu_napiecia_4.1 | length 6.2
  L1 w0.254: U64_U_Pomiar_pradu_napiecia_4.1@268.005,178.019 268.028,178.042 268.028,178.802 268.155,178.929 v8(268.155,178.969)
  L16 w0.254: v8(268.155,178.969) 269.055,179.869 R576.2@269.055,180.907 R575.2@269.055,181.846 R573.2@269.055,182.786 R574.2@269.055,183.751
NetR577_2: R577.2 R578.2 R579.2 R580.2 U64_U_Pomiar_pradu_napiecia_5.2 | length 7.2
  L1 w0.164: v8(220.143,136.12) 220.143,136.057 220.253,135.947 U64_U_Pomiar_pradu_napiecia_5.2@220.253,135.17
  L16 w0.164: R578.2@218.402,141.279 R577.2@218.402,140.072 R579.2@218.402,138.865 R580.2@218.402,137.658 218.402,137.258 219.54,136.12 v8(220.143,136.12)
NetR581_2: R581.2 R582.2 R583.2 R584.2 U64_U_Pomiar_pradu_napiecia_5.1 | length 6.7
  L1 w0.164: U64_U_Pomiar_pradu_napiecia_5.1@220.753,135.17 220.753,135.915 220.909,136.071 v8(220.909,136.12)
  L16 w0.164: v8(220.909,136.12) 222.097,137.308 R584.2@222.097,137.658 222.097,138.854 R583.2@222.108,138.865 R582.2@222.108,141.279
NetR585_2: R585.2 R586.2 R587.2 R588.2 U64_U_Pomiar_pradu_napiecia_6.2 | length 6.7
  L1 w0.254: v8(223.83,126.055) 223.87,126.055 223.997,126.182 224.757,126.182 U64_U_Pomiar_pradu_napiecia_6.2@224.78,126.205
  L16 w0.254: R586.2@218.851,124.405 R588.2@221.959,124.405 ; R588.2@221.959,124.405 221.959,124.455 222.132,124.628 222.403,124.628 v8(223.83,126.055)
NetR589_2: R589.2 R590.2 R591.2 R592.2 U64_U_Pomiar_pradu_napiecia_6.1 | length 6.4
  L1 w0.254: v8(223.83,126.855) 223.87,126.855 223.997,126.728 224.757,126.728 U64_U_Pomiar_pradu_napiecia_6.1@224.78,126.705
  L16 w0.254: R590.2@218.861,127.778 218.864,127.78 221.956,127.78 R592.2@221.959,127.783 222.902,127.783 v8(223.83,126.855)
NetR595_2: R595.2 R596.2 R597.2 R598.2 U64_U_Pomiar_pradu_napiecia_2.1 | length 6.2
  L1 w0.254: U64_U_Pomiar_pradu_napiecia_2.1@54.676,41.783 55.614,41.783 55.815,41.582 v8(55.854,41.582)
  L16 w0.254: v8(55.854,41.582) 56.437,41 R598.2@57.264,41 R596.2@60.53,41
NetR599_1: R599.1 U3_I2C_Bridge_2.19 U35_I2C_Expander?.8 U36_U_Translator_I2C1.6 U36_U_Translator_I2C2.6
  other v1: 469.895,195.896 470.995,195.896 472.095,195.896 473.195,195.896 469.895,196.996 470.995,196.996 472.095,196.996 473.195,196.996 469.895,198.096 470.995,198.096 472.095,198.096 473.195,198.096 469.895,199.196 470.995,199.196 472.095,199.196 473.195,199.196
NetR600_1: R600.1 R601.2 U58.1
NetR607_1: R607.1 U1.AA13
NetR612_1: R612.1 U34.29 | length 8.5
  L1 w0.254: v1(119.019,42.916) 120.397,42.916 120.406,42.906 U34.29@120.477,42.906
  L16 w0.254: v1(116.226,38.001) 117.002,38.001 117.37,38.369 117.37,39 117.938,39.568 117.938,42.767 118.087,42.916 v1(119.019,42.916)
NetR614_1: R614.1 U34.12 | length 6.9
  L1 w0.254: U34.12@124.977,42.906 124.979,42.904 125.128,42.904 125.132,42.899 126.234,42.899 126.383,42.75 126.383,42.194 127.404,41.172 R614.1@127.404,37.776
NetR621_1: R621.1 U37.29 | length 15.1
  L1 w0.254: R621.1@201.912,52.737 202.559,52.737 202.566,52.729 v11(202.566,52.538) ; v11(210.566,42.366) 210.573,42.359 U37.29@211.295,42.359
  L3 (Sign) w0.254: v11(202.566,52.538) 207.267,47.837 207.267,45.666 v11(210.566,42.366)
NetR622_1: R622.1 U37.12 | length 14.5
  L1 w0.254: U37.12@215.795,42.359 216.124,42.359 v11(216.145,42.339) ; v11(224.342,52.437) R622.1@224.947,52.437
  L3 (Sign) w0.254: v11(216.145,42.339) 219.422,45.617 219.422,47.517 v11(224.342,52.437)
NetR628_1: R628.1 U38.12 | length 16
  L1 w0.254: U38.12@168.283,38.515 v11@168.893,38.515 ; v30(176.297,50.245) R628.1@176.922,50.245
  L3 (Sign) w0.254: v11(168.894,38.516) 174.934,44.556 174.934,48.882 v30(176.297,50.245)
NetR644_1: R644.1 R645.2 U69.9 | length 2.4
  L1 w0.254: R644.1@158.898,150.312 R645.2@158.898,151.5 158.938,151.46 160.02,151.46 U69.9@160.043,151.437
NetR648_2: R648.2 T25.3
NetR650_2: R650.2 T23.1 T24.3
NetR651_1: R651.1 T27.1 T28.3
NetR653_2: R653.2 T30.3
NetR655_1: R655.1 T29.1
NetR657_2: R657.2 T31.3
NetR658_1: R658.1 T31.1
NetR665_2: R665.2 U65.13 | length 6
  L1 w0.254: U65.13@54.172,81.207 55.223,81.207 55.938,80.491 55.938,78.6 56.654,77.884 R665.2@57.678,77.884
NetR677_1: R677.1 R682.2 U48.6 | length 2.1
  L1 w0.254: R677.1@67.235,35.022 R682.2@67.235,34.081 67.235,33.09 67.267,33.058 U48.6@67.267,32.912
NetR678_1: R678.1 R683.2 U48.5 | length 4.3
  L1 w0.254: R683.2@67.235,36.958 67.235,36.022 67.812,35.445 67.812,33.103 67.767,33.058 U48.5@67.767,32.912
NetR679_1: R679.1 R684.2 U48.3 | length 2.2
  L1 w0.254: U48.3@68.767,32.912 68.769,32.914 68.769,33.961 R679.1@68.849,34.041 68.854,34.046 68.854,35.027 R684.2@68.859,35.032
NetR680_1: R680.1 R685.2 U48.4 | length 4.4
  L1 w0.254: U48.4@68.267,32.912 68.267,35.511 68.809,36.052 R680.1@68.859,36.052 68.856,36.055 68.856,37.015 R685.2@68.853,37.017
NetR681_2: R681.2 U48.10 | length 1.4
  L1 w0.254: U48.10@67.767,30.612 67.767,29.657 68.053,29.371 R681.2@68.053,29.321
NetR686_1: R686.1 U38.29 | length 15.8
  L1 w0.254: R686.1@155.653,50.245 v11(156.259,50.245) ; v11(163.221,38.515) U38.29@163.783,38.515
  L3 (Sign) w0.254: v11(156.259,50.245) 157.093,49.411 157.093,44.643 v11(163.221,38.515)
NetR689_2: R689.2 R690.2 U73.7 | length 2.4
  L1 w0.254: U73.7@218.551,210.633 218.651,210.633 218.675,210.657 R689.2@219.964,210.657 R690.2@220.929,210.657
NetR692_1: R692.1 S6.3 S6.4
NetR710_1: R710.1 R711.1 R712.2
NetR711_2: R711.2 U76.4
NetR713_1: R713.1 S7.1 S7.2
NetR714_2: R714.2 S7.3 S7.4
NetR736_1: R736.1 U1.AB13
NetR738_1: R738.1 R739.1 U35_I2C_Expander2.13 | length 7.4
  L1 w0.254: 490.04,229.565 491.33,229.565 492.63,228.265 494.167,228.265 494.517,228.615 R738.1@494.517,229.065 R739.1@496.333,229.065
NetR740_1: R740.1 R741.1 U35_I2C_Expander2.12 | length 7.3
  L1 w0.254: U35_I2C_Expander2.12@490.04,230.215 490.06,230.194 v1(492.106,230.194) ; R740.1@494.517,230.174 494.538,230.194 v1(495.467,230.194) 495.477,230.184 496.323,230.184 R741.1@496.333,230.174
  L14 (Sign) w0.254: v1(492.106,230.194) v1(495.467,230.194)
NetR742_1: R742.1 R743.1 U35_I2C_Expander2.11 | length 7.4
  L1 w0.254: 490.04,230.865 491.495,230.865 492.63,232.001 494.167,232.001 494.492,231.676 494.492,231.224 R742.1@494.517,231.199 R743.1@496.333,231.199
NetR753_1: R753.1 U3_I2C_Bridge.24 U35_I2C_Expander?.4
NetR754_1: R754.1 U35_I2C_Expander2.14 U35_I2C_Expander?.23
NetR758_1: R758.1 R759.1 U35_I2C_Expander?.13 | length 7.2
  L1 w0.254: 474.42,197.546 475.195,197.546 476.495,196.246 478.008,196.246 478.213,196.451 R758.1@478.213,197.199 479.404,197.199 479.414,197.189 R759.1@480.204,197.189
NetR760_1: R760.1 R761.1 U35_I2C_Expander?.12 | length 6.9
  L1 w0.254: U35_I2C_Expander?.12@474.42,198.196 474.43,198.206 v1(475.947,198.206) ; R760.1@478.214,198.206 v1(479.292,198.206) 479.297,198.201 480.2,198.201 R761.1@480.204,198.196
  L14 (Sign) w0.254: v1(475.947,198.206) v1(479.292,198.206)
NetR762_1: R762.1 R763.1 U35_I2C_Expander?.11 | length 7
  L1 w0.254: 474.42,198.846 475.15,198.846 476.35,200.046 478.008,200.046 478.214,199.84 R762.1@478.214,199.196 479.404,199.196 479.414,199.187 R763.1@480.204,199.187
NetR765_1: R765.1 U1.AE14
NetR766_1: R766.1 U1.AE13
NetR766_2: R766.2
NetR767_1: R767.1 U1.AC14
NetR767_2: R767.2
NetR768_1: R768.1
NetR769_1: R769.1
NetR770_1: R770.1
NetR771_1: R771.1
NetR836_2: R836.2 R838.1 U35_I2C_Expander_16.22
NetR837_2: R837.2 R840.1 U35_I2C_Expander_16.19
NetR839_2: R839.2 R841.1 U35_I2C_Expander_16.17
NetT22_3: T22.3 T23.2
NetT34_4: T34.4 U65.11 | length 16.6
  L1 w0.254: U65.11@54.172,80.207 55.023,80.207 v9(55.025,80.204)
  L16 w0.254: v9(55.025,80.204) 62.577,87.757 v9(67.63,87.757)
NetT35_4: T35.4 U65.15 | length 9.8
  L1 w0.254: U65.15@54.172,82.207 v11(54.875,82.207) ; v11(61.493,78.15) T35.4@62.331,78.15
  L3 (Sign) w0.254: v11(54.875,82.207) 58.931,78.15 v11(61.493,78.15)
NetTP7_I2C_Bridge_2_1: U3_I2C_Bridge_2.24 U35_I2C_Expander?.26
NetU1_AJ1: U1.AJ1
NetU1_AJ2: U1.AJ2
NetU1_D9: U1.D9
NetU1_D10: U1.D10
NetU3_I2C_Bridge_3_19: U3_I2C_Bridge_3.19 U36_U_Translator_I2C3.6 U36_U_Translator_I2C4.6
NetU3_I2C_Bridge_3_20: U3_I2C_Bridge_3.20 U36_U_Translator_I2C3.5 U36_U_Translator_I2C4.5
NetU24_SPI_bridge1_3: U24_SPI_bridge1.3 U25_SPI_bridge1.3 U25_SPI_bridge3.14 U26_SPI_bridge1.3 U27_SPI_bridge1.3 U28_SPI_bridge1.3
NetU24_SPI_bridge1_4: U24_SPI_bridge1.4 U25_SPI_bridge1.4 U25_SPI_bridge3.13 U26_SPI_bridge1.4 U27_SPI_bridge1.4 U28_SPI_bridge1.4
NetU24_SPI_bridge1_5: U24_SPI_bridge1.5 U25_SPI_bridge1.5 U25_SPI_bridge3.12 U26_SPI_bridge1.5 U27_SPI_bridge1.5 U28_SPI_bridge1.5
NetU24_SPI_bridge3_12: U24_SPI_bridge3.12
NetU24_SPI_bridge3_13: U24_SPI_bridge3.13
NetU24_SPI_bridge3_14: U24_SPI_bridge3.14
NetU27_SPI_bridge2_12: U27_SPI_bridge2.12
NetU27_SPI_bridge2_13: U27_SPI_bridge2.13
NetU27_SPI_bridge2_14: U27_SPI_bridge2.14
NetU27_SPI_bridge3_12: U27_SPI_bridge3.12
NetU27_SPI_bridge3_13: U27_SPI_bridge3.13
NetU27_SPI_bridge3_14: U27_SPI_bridge3.14
NetU28_SPI_bridge3_12: U28_SPI_bridge3.12
NetU28_SPI_bridge3_13: U28_SPI_bridge3.13
NetU28_SPI_bridge3_14: U28_SPI_bridge3.14
NetU35_I2C_Expander1_1: U35_I2C_Expander1.1
NetU35_I2C_Expander1_25: U35_I2C_Expander1.25
NetU35_I2C_Expander1_26: U35_I2C_Expander1.26
NetU35_I2C_Expander1_27: U35_I2C_Expander1.27
NetU35_I2C_Expander1_28: U35_I2C_Expander1.28
NetU35_I2C_Expander2_15: U35_I2C_Expander2.15
NetU35_I2C_Expander2_16: U35_I2C_Expander2.16
NetU35_I2C_Expander2_25: U35_I2C_Expander2.25
NetU35_I2C_Expander2_26: U35_I2C_Expander2.26
NetU35_I2C_Expander2_27: U35_I2C_Expander2.27
NetU35_I2C_Expander3_20: U35_I2C_Expander3.20
NetU35_I2C_Expander3_22: U35_I2C_Expander3.22
NetU35_I2C_Expander3_23: U35_I2C_Expander3.23
NetU35_I2C_Expander3_25: U35_I2C_Expander3.25
NetU35_I2C_Expander?_17: U35_I2C_Expander?.17
NetU35_I2C_Expander?_27: U35_I2C_Expander?.27
NetU35_I2C_Expander_10_27: U35_I2C_Expander_10.27
NetU35_I2C_Expander_12_26: U35_I2C_Expander_12.26
NetU35_I2C_Expander_12_27: U35_I2C_Expander_12.27
NetU35_I2C_Expander_13_2: U35_I2C_Expander_13.2
NetU35_I2C_Expander_13_17: U35_I2C_Expander_13.17
NetU35_I2C_Expander_13_18: U35_I2C_Expander_13.18
NetU35_I2C_Expander_13_20: U35_I2C_Expander_13.20
NetU35_I2C_Expander_13_26: U35_I2C_Expander_13.26
NetU35_I2C_Expander_13_27: U35_I2C_Expander_13.27
NetU35_I2C_Expander_14_17: U35_I2C_Expander_14.17
NetU35_I2C_Expander_14_25: U35_I2C_Expander_14.25
NetU35_I2C_Expander_14_26: U35_I2C_Expander_14.26
NetU35_I2C_Expander_15_4: U35_I2C_Expander_15.4
NetU35_I2C_Expander_15_17: U35_I2C_Expander_15.17
NetU35_I2C_Expander_15_23: U35_I2C_Expander_15.23
NetU35_I2C_Expander_15_24: U35_I2C_Expander_15.24
NetU35_I2C_Expander_16_1: U35_I2C_Expander_16.1
NetU35_I2C_Expander_16_4: U35_I2C_Expander_16.4
NetU35_I2C_Expander_16_23: U35_I2C_Expander_16.23
NetU35_I2C_Expander_16_24: U35_I2C_Expander_16.24
NetU35_I2C_Expander_16_25: U35_I2C_Expander_16.25
NetU35_I2C_Expander_16_26: U35_I2C_Expander_16.26
NetU35_I2C_Expander_16_27: U35_I2C_Expander_16.27
NetU35_I2C_Expander_16_28: U35_I2C_Expander_16.28
NetU36_U_Translator_I2C1_8: U36_U_Translator_I2C1.8
NetU36_U_Translator_I2C4_8: U36_U_Translator_I2C4.8
NVME_C_RX_1_N: C718.1 U1.K28
NVME_C_RX_1_P: C717.1 U1.K27
NVME_C_RX_O_N: C677.1 U1.M28
NVME_C_RX_O_P: C653.1 U1.M27
NVME_C_TX_1_N: C716.1 U1.J30
NVME_C_TX_1_P: C715.1 U1.J29
NVME_C_TX_O_N: C651.1 U1.L30
NVME_C_TX_O_P: C649.1 U1.L29
NVMe_Rx_0_N: C677.2 J27.47 R541.1
NVMe_Rx_0_P: C653.2 J27.49 R541.2
NVMe_Rx_1_N: C718.2 J27.35 R542.1
NVMe_Rx_1_P: C717.2 J27.37 R542.2
NVMe_Tx_0_N: C651.2 J27.41
NVMe_Tx_0_P: C649.2 J27.43
NVMe_Tx_1_N: C716.2 J27.29
NVMe_Tx_1_P: C715.2 J27.31
OSC_500Out: C333.2 X2.10 | length 3.2
  L3 (Sign) w0.254: v25(419.252,351.917) v26(422.427,351.917)
  other v25: 422.427,351.917
  other v26: 419.252,351.917
Osc_in_Si53323_2_N: C343.2 R259.2 R261.2 R489.1 U32.6
Osc_in_Si53323_2_P: C342.2 R260.2 R262.2 R489.2 U32.7
OSC_Out_DIV_N: C343.1 R258.1 U33.11
OSC_Out_DIV_P: C342.1 R256.2 U33.10
PCIE0_CLK_N: J1_PCIE0.53
PCIE0_CLK_P: J1_PCIE0.55
PCIE0_En_DCDC: J1_PCIE0.36 U35_I2C_Expander_11.22
PCIE0_Prsnt1: J1_PCIE0.12 U35_I2C_Expander_12.28
PCIE0_Prsnt2: U35_I2C_Expander_12.25
PCIE0_Reset: J1_PCIE0.32 U35_I2C_Expander_11.19
PCIE0_SysRef_FPGA_N: U1.AG10
PCIE0_SysRef_FPGA_P: U1.AF10
PCIE0_SysRef_N: J1_PCIE0.52
PCIE0_SysRef_P: J1_PCIE0.50
PCIE1_CLK_N: 
PCIE1_CLK_P: 
PCIE1_En_DCDC: U35_I2C_Expander_11.23
PCIE1_Prsnt1: U35_I2C_Expander_11.1
PCIE1_Prsnt2: U35_I2C_Expander_11.17
PCIE1_Reset: U35_I2C_Expander_11.24
  other v1: 486.479,207.811 487.579,207.811 488.679,207.811 489.779,207.811 486.479,208.911 487.579,208.911 488.679,208.911 489.779,208.911 486.479,210.011 487.579,210.011 488.679,210.011 489.779,210.011 486.479,211.111 487.579,211.111 488.679,211.111 489.779,211.111
PCIE1_SysRef_FPGA_N: U1.AK8
PCIE1_SysRef_FPGA_P: U1.AK9
PCIE1_SysRef_N: 
PCIE1_SysRef_P: 
PCIE2_CLK_N: J1_PCIE2.53 U14.6
PCIE2_CLK_P: J1_PCIE2.55 U14.7
PCIE2_En_DCDC: J1_PCIE2.36 U35_I2C_Expander_11.25
PCIE2_Prsnt1: J1_PCIE2.12 U35_I2C_Expander_11.27
PCIE2_Prsnt2: U35_I2C_Expander_12.21
PCIE2_Reset: J1_PCIE2.32 U35_I2C_Expander_11.26
PCIE2_SysRef_FPGA_N: U1.AJ9 U14.30
PCIE2_SysRef_FPGA_P: U1.AH9 U14.31
PCIE2_SysRef_N: J1_PCIE2.52 U14.3
PCIE2_SysRef_P: J1_PCIE2.50 U14.4
PCIE3_CLK_N: U14.15
PCIE3_CLK_P: U14.16
PCIE3_En_DCDC: U35_I2C_Expander_12.2
PCIE3_Prsnt1: U35_I2C_Expander_12.3
PCIE3_Prsnt2: U35_I2C_Expander_12.22
PCIE3_Reset: U35_I2C_Expander_12.18
PCIE3_SysRef_FPGA_N: U1.AF7 U14.27
PCIE3_SysRef_FPGA_P: U1.AF8 U14.28
PCIE3_SysRef_N: U14.9
PCIE3_SysRef_P: U14.10
PCIE4_CLK_N: J1_PCIE4.53 U14.21
PCIE4_CLK_P: J1_PCIE4.55 U14.22
PCIE4_En_DCDC: J1_PCIE4.36 U35_I2C_Expander_12.17
PCIE4_Prsnt1: J1_PCIE4.12 U35_I2C_Expander_12.23
PCIE4_Prsnt2: U35_I2C_Expander_12.24
PCIE4_Reset: J1_PCIE4.32 U35_I2C_Expander_12.4
PCIE4_SysRef_FPGA_N: U1.AE8 U14.24
PCIE4_SysRef_FPGA_P: U1.AE9 U14.25
PCIE4_SysRef_N: J1_PCIE4.52 U14.18
PCIE4_SysRef_P: J1_PCIE4.50 U14.19
PCIe_Reset: R788.1
PDN: R498.2 U16.46
PDN_LMK05028: R499.1 U35_I2C_Expander_14.27
PEDET: J27.61
PERST#: J27.50
PEwake: J27.54
PG1_1: R295.2 R836.1 R839.1 U37.27 | length 1.4
  L1 w0.254: R295.2@209.891,43.359 U37.27@211.295,43.359
PG1_2: R313.2 U38.27 | length 1.8
  L1 w0.254: R313.2@162.193,40.015 162.721,40.015 163.221,39.515 U38.27@163.783,39.515
PG1_TPS7A8801: R440.1 U35_I2C_Expander2.1 U61.17 | length 4.6
  L1 w0.254: R440.1@230.82,137.821 230.87,137.771 v11(231.07,137.771) ; v11(233.692,137.138) U61.17@233.692,138.03
  L3 (Sign) w0.254: v11(231.07,137.771) 232.225,136.616 233.407,136.616 233.692,136.901 v11(233.692,137.138)
PG2_2: R314.2 R837.1 U38.14 | length 1.6
  L1 w0.254: U38.14@168.283,39.515 168.285,39.517 169.606,39.517 R314.2@169.774,39.685
PG2_TPS7A8801: R441.1 U35_I2C_Expander2.28 U61.9 | length 4.7
  L1 w0.254: U61.9@233.692,141.98 v11(233.692,142.578)
  L3 (Sign) w0.254: v11(229.707,142.827) 233.442,142.827 v11(233.692,142.578)
PG2_TPS7A8801_0V9: R676.1 U37.8 U70.9 U73.5 | length 3
  L1 w0.254: U70.9@298.759,169.748 298.759,168.033 299.431,167.361 299.431,167.311 299.604,167.138 R676.1@299.654,167.138
PG_1V0@1.5A: R834.2 U35_I2C_Expander_16.20 U51.5 | length 4.4
  L1 w0.254: U51.5@185.559,121.563 U51.5@185.684,121.563 ; v8(189.244,122.7) 189.244,123.125
  L16 w0.254: v8(185.859,121.563) 188.108,121.563 v8(189.244,122.7)
PG_1V8@1.5A: R833.2 U35_I2C_Expander_16.21 U50.5 | length 4.3
  L1 w0.254: U50.5@185.559,126.81 185.589,126.81 U50.5@185.637,126.762 ; v8(189.244,127.829) 189.244,128.254
  L16 w0.254: v8(185.859,126.81) 188.226,126.81 v8(189.244,127.829)
PG_2V5@1.5A: R392.1 U18.A2 U49.5 | length 4.4
  L1 w0.254: v8(189.711,132.07) R392.1@189.711,132.495
  L16 w0.254: v8(185.859,131.659) 186.269,132.07 v8(189.711,132.07)
PG_48_20V: R835.2 U35_I2C_Expander_16.18 U65.19 | length 6.6
  L1 w0.254: U65.19@51.832,83.047 v9(51.832,83.914)
  L16 w0.254: v9(47.095,81.529) 49.447,81.529 v9(51.832,83.914)
PG_DCDC_Low_curr: R832.2 U19.23 U35_I2C_Expander_16.3
PG_LT3042: R442.1 U62.4 | length 1.2
  L1 w0.254: R442.1@419.739,341.217 420.559,341.217 420.684,341.342 U62.4@420.905,341.342
PG_PS_LN_5V0_1: U35_I2C_Expander2.4
PG_PS_LTC6952_1: R431_U_5V_to_3V33.1 U35_I2C_Expander2.21 U59_U_5V_to_3V33.5 | length 2.1
  L1 w0.254: U59_U_5V_to_3V33.5@292.231,67.334 292.25,67.334 292.298,67.286 292.298,66.858 292.553,66.603 R431_U_5V_to_3V33.1@293.804,66.603
PG_PS_LTC6952_2: R431_U_5V_to_3V32.1 U35_I2C_Expander2.3 U59_U_5V_to_3V32.5 | length 4
  L1 w0.254: R431_U_5V_to_3V32.1@278.329,63.034 v11(278.329,63.459) ; v11(280.919,64.483) 280.945,64.509 U59_U_5V_to_3V32.5@281.454,64.509
  L3 (Sign) w0.254: v11(278.329,63.459) 279.353,64.483 v11(280.919,64.483)
PG_PS_LTC6952_3: R431_U_5V_to_3V31.1 U35_I2C_Expander2.19 U59_U_5V_to_3V31.5 | length 1.6
  L1 w0.254: R431_U_5V_to_3V31.1@280.259,69.409 280.712,69.409 281.162,68.959 U59_U_5V_to_3V31.5@281.697,68.959
PG_VTT_RAM: R691.2 U35_I2C_Expander_16.2 U73.6 | length 5.8
  L1 w0.254: v8(213.741,208.657) R691.2@213.741,208.783
  L16 w0.254: v8@213.741,208.678 217.346,208.678 v8(218.801,210.133)
PGND: C595.1 C596.1 C597.1 C598.1 C694.1 C695.1 C696.1 C697.1 C698.1 C699.1 C700.1 C704.2 D3.2 D4.2 R324.1 R764.2 T35.1 T35.2 T35.3 U65.16
  other v5: 87.728,76.455 86.59,76.69 77.658,76.765 79.463,76.768 81.218,76.769 83.04,76.769 84.868,76.765 54.875,88.707 53.697,88.717 56.704,88.717 59.628,88.717 58.578,88.769 57.778,89.344 58.578,89.344 59.628,89.344 53.697,89.357 54.875,89.357 55.675,89.357 56.386,89.367 57.146,89.367 54.121,89.98 54.875,89.98 55.655,89.98 56.386,89.98 57.128,89.98 57.787,89.98 58.578,89.98 59.203,89.98
  other v7: 76.5,76.5 87.375,77.25 76.5,78 77.25,78 78,78 78.75,78 79.5,78 80.25,78 81,78 81.75,78 82.5,78 83.25,78 84,78 84.75,78 85.5,78 86.25,78 87,78 76.875,78.75 77.625,78.75 78.375,78.75 79.125,78.75 79.875,78.75 80.625,78.75 81.375,78.75 82.125,78.75 82.875,78.75 83.625,78.75 84.375,78.75 85.125,78.75 85.875,78.75 86.625,78.75
PMU_GPI: J14.7 R784.1
PMU_GPI_1: J14.6 R785.1
PMU_GPI_2: J14.5 R786.1
PMU_GPI_3: J14.4 R787.1
PMU_GPI_5: J14.2 R789.1
PMU_GPO_0: J18.7 R790.1
PMU_GPO_1: J18.6 R791.1
PMU_GPO_2: J18.5 R792.1
PMU_GPO_3: J18.4 R793.1
PMU_GPO_4: J18.3 R794.1
PMU_GPO_5: J18.2 R795.1
Power1_In: P8.1 R448_U_Pomiar_pradu_napiecia_1.1 U64_U_Pomiar_pradu_napiecia_1.10
Power1_In_CM: R12.2 R448_U_Pomiar_pradu_napiecia_1.2 U5.7 U6.C3 U6.D3 U6.D4 U6.E3 U6.E4 U6.F3 U6.F4 U64_U_Pomiar_pradu_napiecia_1.8 U64_U_Pomiar_pradu_napiecia_1.9
  other v12: 67.229,53.795
Power2_In: P10.1 R448_U_Pomiar_pradu_napiecia_2.1 U64_U_Pomiar_pradu_napiecia_2.10
Power2_In_CM: R20.2 R448_U_Pomiar_pradu_napiecia_2.2 U5.2 U7.C3 U7.D3 U7.D4 U7.E3 U7.E4 U7.F3 U7.F4 U64_U_Pomiar_pradu_napiecia_2.8 U64_U_Pomiar_pradu_napiecia_2.9
  other v12: 68.029,53.795
Power4Charging: U6.C2 U6.D1 U6.D2 U6.E1 U6.E2 U6.F1 U6.F2 U7.C2 U7.D1 U7.D2 U7.E1 U7.E2 U7.F1 U7.F2
Power_3.3_1: C99.2 C100.2 C103.2 C104.2 C107.2 C124.2 C141.2 C145.2 C162.2 C179.2 C572.2 C573.2 FB8.1 FB9.1 FB10.1 FB11.1 FB12.1 FB14.1 FB16.1 FB18.1 FB20.1 FB22.1 R436.2 R440.2 U61.14 U61.15
Power_3.3_2: C108.2 C125.2 C142.2 C146.2 C163.2 C576.2 C577.2 FB13.1 FB15.1 FB17.1 FB19.1 FB21.1 R438.2 R441.2 U61.11 U61.12
Power_MUX_Status0: R13.2 U5.9 U35_I2C_Expander1.21 | length 1.2
  L1 w0.254: R13.2@66.879,51.111 U5.9@66.879,52.295
Power_MUX_Status1: R11.2 U4.9 U35_I2C_Expander1.20 | length 1.3
  L1 w0.254: R11.2@67.052,39.6 67.056,39.605 67.056,40.845 U4.9@67.06,40.85
Power_MUX_Status2: R630.2 U35_I2C_Expander1.4 U48.9 | length 1.4
  L1 w0.254: R630.2@67.085,29.321 67.085,30.284 67.267,30.466 U48.9@67.267,30.612
PS_MODE1: P2.3 R350.1 S1.2 U1.R19 U74.2
PS_POR: P3.2 R355.2 U1.N19 U74.1 U76.1 U77.6
PS_Reset: P4.1 R354.1 U1.P20 U77.4 U78.6
PSIO_VOLTAGE_3V3: U57.15
PWR_ExtIO_nReset: R755.1 U35_I2C_Expander1.14 U35_I2C_Expander?.24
